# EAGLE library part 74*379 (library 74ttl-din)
Quad D type FLIP FLOP, enable
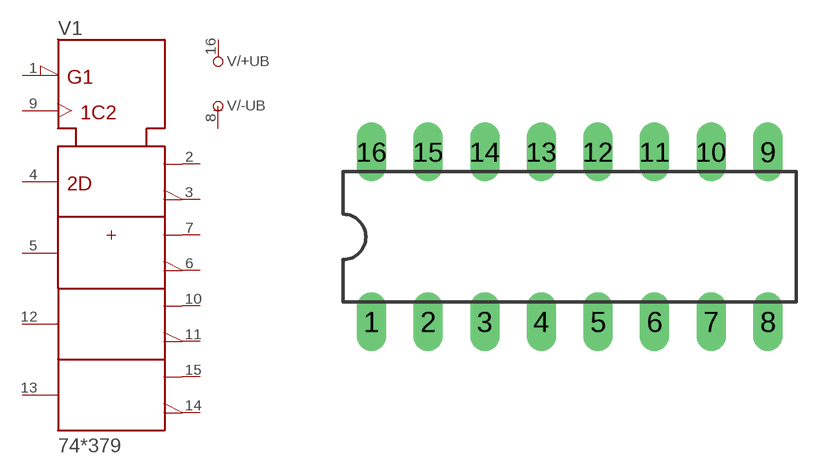
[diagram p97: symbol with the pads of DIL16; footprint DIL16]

Designator prefix V; gates /+UB=+UB /-UB=-UB 1=379

## 74379N  [DIL16]
1  1:G\  in
2  1:1Q  out
3  1:1Q\  out
4  1:1D  in
5  1:2D  in
6  1:2Q\  out
7  1:2Q  out
8  /-UB:-UB  pwr
9  1:CLK  in
10  1:3Q  out
11  1:3Q\  out
12  1:3D  in
13  1:4D  in
14  1:4Q\  out
15  1:4Q  out
16  /+UB:+UB  pwr

## Footprint DIL16 (pad centres in mm)
Dual In Line Package
drill 0.813 long: 1 -8.89,-3.81; 2 -6.35,-3.81; 3 -3.81,-3.81; 4 -1.27,-3.81; 5 1.27,-3.81; 6 3.81,-3.81; 7 6.35,-3.81; 8 8.89,-3.81; 9 8.89,3.81; 10 6.35,3.81; 11 3.81,3.81; 12 1.27,3.81; 13 -1.27,3.81; 14 -3.81,3.81; 15 -6.35,3.81; 16 -8.89,3.81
